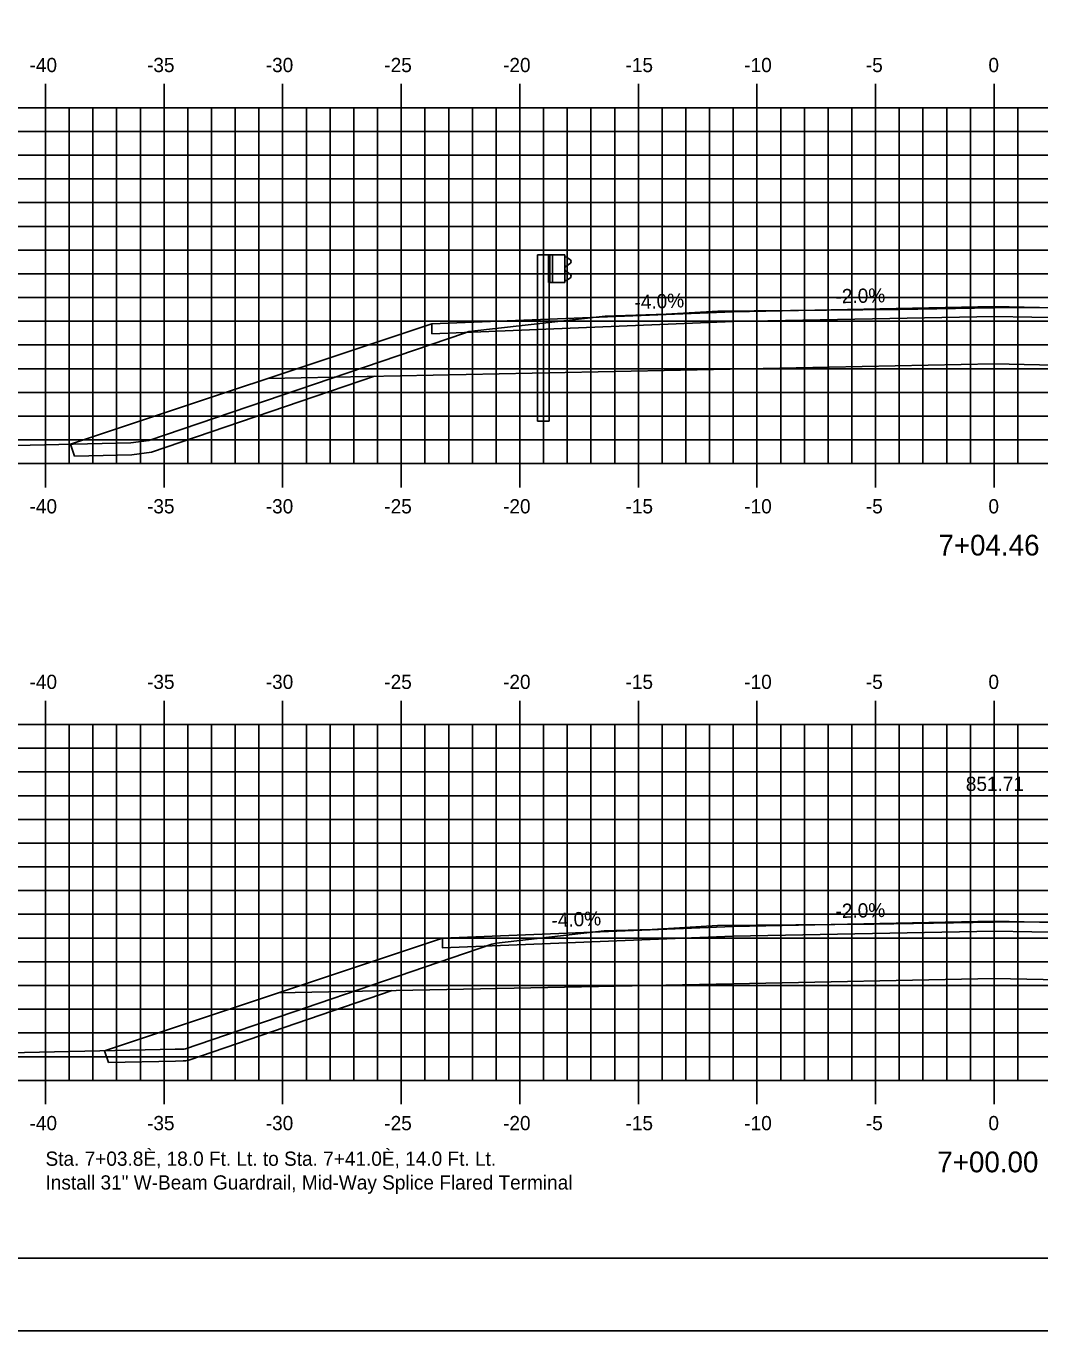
# Model space of a CAD drawing. Extents: x 2194004 to 2194525, y 863888 to 863998.
# Drawn here: x 2194214.2 to 2194256.9, y 863888.4 to 863943.4 of the extents above; entities that cross this region are included whole.
import ezdxf

# ---------------------------------------------------------------- set-up
doc = ezdxf.new("R2010")
doc.units = 0
for name, color, linetype in [('ANNOTATION', 7, 'Continuous'), ('BORDER', 7, 'Continuous'), ('D_Guardrail_Beam_Lt', 7, 'Continuous'), ('H_V ANNOTATION', 7, 'Continuous'), ('MAJOR', 7, 'Continuous'), ('MINOR', 7, 'Continuous'), ('PLOT BOUNDARY', 7, 'Continuous'), ('S_Roadway_Centerline', 7, 'Continuous'), ('TEMPLATE', 7, 'Continuous')]:
    doc.layers.add(name, color=color, linetype=linetype)

msp = doc.modelspace()

# ---------------------------------------------------------------- linework, layer by layer
at = {"layer": 'BORDER'}
msp.add_lwpolyline([(2194179.986, 863891.446), (2194339.986, 863891.446), (2194339.986, 863996.446), (2194179.986, 863996.446)], close=True, dxfattribs=at)
at = {"layer": 'D_Guardrail_Beam_Lt'}
for p, q in [((2194235.725, 863933.739), (2194235.725, 863926.739)), ((2194236.196, 863933.739), (2194235.725, 863933.739)), ((2194236.883, 863933.739), (2194236.196, 863933.739)), ((2194236.196, 863933.739), (2194236.196, 863932.572)), ((2194236.258, 863933.739), (2194236.258, 863932.572)), ((2194236.363, 863933.739), (2194236.363, 863932.572)), ((2194236.883, 863932.572), (2194236.883, 863933.739)), ((2194236.883, 863933.656), (2194236.958, 863933.641)), ((2194236.973, 863933.635), (2194237.117, 863933.535)), ((2194236.888, 863933.191), (2194236.888, 863933.121)), ((2194237.117, 863933.391), (2194236.921, 863933.255)), ((2194236.921, 863933.056), (2194237.117, 863932.92)), ((2194236.196, 863932.572), (2194236.883, 863932.572)), ((2194236.217, 863926.739), (2194236.217, 863932.572)), ((2194236.958, 863932.67), (2194236.883, 863932.656)), ((2194237.117, 863932.777), (2194236.973, 863932.677)), ((2194236.217, 863926.739), (2194235.725, 863926.739))]:
    msp.add_line(p, q, dxfattribs=at)
for centre, major_axis, start_param, end_param in [((2194236.949, 863933.601), (0.0417, 0), 0.959931, 1.376053), ((2194237.066, 863933.463), (0.0877, 0), 5.323254, 7.243116), ((2194236.967, 863933.191), (-0.0789, 0), 5.323254, 6.283185), ((2194236.967, 863933.121), (-0.0789, 0), 6.283185, 7.243116), ((2194237.066, 863932.849), (0.0877, 0), 5.323254, 7.243116), ((2194236.949, 863932.711), (0.0417, 0), 4.907132, 5.323254)]:
    msp.add_ellipse(centre, major_axis=major_axis, ratio=0.995501, start_param=start_param, end_param=end_param, dxfattribs=at)
at = {"layer": 'MAJOR'}
for p, q in [((2194214.986, 863940.948), (2194214.986, 863939.946)), ((2194219.986, 863940.948), (2194219.986, 863939.946)), ((2194224.986, 863940.948), (2194224.986, 863939.946)), ((2194229.986, 863940.948), (2194229.986, 863939.946)), ((2194234.986, 863940.948), (2194234.986, 863939.946)), ((2194239.986, 863940.948), (2194239.986, 863939.946)), ((2194244.986, 863940.948), (2194244.986, 863939.946)), ((2194249.986, 863940.948), (2194249.986, 863939.946)), ((2194254.986, 863940.948), (2194254.986, 863939.946)), ((2194184.986, 863939.946), (2194324.986, 863939.946)), ((2194184.986, 863939.946), (2194324.986, 863939.946)), ((2194214.986, 863924.946), (2194214.986, 863939.946)), ((2194219.986, 863924.946), (2194219.986, 863939.946)), ((2194224.986, 863924.946), (2194224.986, 863939.946)), ((2194229.986, 863924.946), (2194229.986, 863939.946)), ((2194234.986, 863924.946), (2194234.986, 863939.946)), ((2194239.986, 863924.946), (2194239.986, 863939.946)), ((2194244.986, 863924.946), (2194244.986, 863939.946)), ((2194249.986, 863924.946), (2194249.986, 863939.946)), ((2194254.986, 863924.946), (2194254.986, 863939.946)), ((2194184.986, 863934.946), (2194324.986, 863934.946)), ((2194184.986, 863929.946), (2194324.986, 863929.946)), ((2194184.986, 863924.946), (2194324.986, 863924.946)), ((2194214.986, 863923.944), (2194214.986, 863924.946)), ((2194219.986, 863923.944), (2194219.986, 863924.946)), ((2194224.986, 863923.944), (2194224.986, 863924.946)), ((2194229.986, 863923.944), (2194229.986, 863924.946)), ((2194234.986, 863923.944), (2194234.986, 863924.946)), ((2194239.986, 863923.944), (2194239.986, 863924.946)), ((2194244.986, 863923.944), (2194244.986, 863924.946)), ((2194249.986, 863923.944), (2194249.986, 863924.946)), ((2194254.986, 863923.944), (2194254.986, 863924.946)), ((2194214.986, 863914.948), (2194214.986, 863913.946)), ((2194219.986, 863914.948), (2194219.986, 863913.946)), ((2194224.986, 863914.948), (2194224.986, 863913.946)), ((2194229.986, 863914.948), (2194229.986, 863913.946)), ((2194234.986, 863914.948), (2194234.986, 863913.946)), ((2194239.986, 863914.948), (2194239.986, 863913.946)), ((2194244.986, 863914.948), (2194244.986, 863913.946)), ((2194249.986, 863914.948), (2194249.986, 863913.946)), ((2194254.986, 863914.948), (2194254.986, 863913.946)), ((2194184.986, 863913.946), (2194324.986, 863913.946)), ((2194184.986, 863913.946), (2194324.986, 863913.946)), ((2194214.986, 863898.946), (2194214.986, 863913.946)), ((2194219.986, 863898.946), (2194219.986, 863913.946)), ((2194224.986, 863898.946), (2194224.986, 863913.946)), ((2194229.986, 863898.946), (2194229.986, 863913.946)), ((2194234.986, 863898.946), (2194234.986, 863913.946)), ((2194239.986, 863898.946), (2194239.986, 863913.946)), ((2194244.986, 863898.946), (2194244.986, 863913.946)), ((2194249.986, 863898.946), (2194249.986, 863913.946)), ((2194254.986, 863898.946), (2194254.986, 863913.946)), ((2194184.986, 863908.946), (2194324.986, 863908.946)), ((2194184.986, 863903.946), (2194324.986, 863903.946)), ((2194184.986, 863898.946), (2194324.986, 863898.946)), ((2194214.986, 863897.944), (2194214.986, 863898.946)), ((2194219.986, 863897.944), (2194219.986, 863898.946)), ((2194224.986, 863897.944), (2194224.986, 863898.946)), ((2194229.986, 863897.944), (2194229.986, 863898.946)), ((2194234.986, 863897.944), (2194234.986, 863898.946)), ((2194239.986, 863897.944), (2194239.986, 863898.946)), ((2194244.986, 863897.944), (2194244.986, 863898.946)), ((2194249.986, 863897.944), (2194249.986, 863898.946)), ((2194254.986, 863897.944), (2194254.986, 863898.946))]:
    msp.add_line(p, q, dxfattribs=at)
at = {"layer": 'MINOR'}
for p, q in [((2194215.986, 863924.946), (2194215.986, 863939.946)), ((2194216.986, 863924.946), (2194216.986, 863939.946)), ((2194217.986, 863924.946), (2194217.986, 863939.946)), ((2194218.986, 863924.946), (2194218.986, 863939.946)), ((2194220.986, 863924.946), (2194220.986, 863939.946)), ((2194221.986, 863924.946), (2194221.986, 863939.946)), ((2194222.986, 863924.946), (2194222.986, 863939.946)), ((2194223.986, 863924.946), (2194223.986, 863939.946)), ((2194225.986, 863924.946), (2194225.986, 863939.946)), ((2194226.986, 863924.946), (2194226.986, 863939.946)), ((2194227.986, 863924.946), (2194227.986, 863939.946)), ((2194228.986, 863924.946), (2194228.986, 863939.946)), ((2194230.986, 863924.946), (2194230.986, 863939.946)), ((2194231.986, 863924.946), (2194231.986, 863939.946)), ((2194232.986, 863924.946), (2194232.986, 863939.946)), ((2194233.986, 863924.946), (2194233.986, 863939.946)), ((2194235.986, 863924.946), (2194235.986, 863939.946)), ((2194236.986, 863924.946), (2194236.986, 863939.946)), ((2194237.986, 863924.946), (2194237.986, 863939.946)), ((2194238.986, 863924.946), (2194238.986, 863939.946)), ((2194240.986, 863924.946), (2194240.986, 863939.946)), ((2194241.986, 863924.946), (2194241.986, 863939.946)), ((2194242.986, 863924.946), (2194242.986, 863939.946)), ((2194243.986, 863924.946), (2194243.986, 863939.946)), ((2194245.986, 863924.946), (2194245.986, 863939.946)), ((2194246.986, 863924.946), (2194246.986, 863939.946)), ((2194247.986, 863924.946), (2194247.986, 863939.946)), ((2194248.986, 863924.946), (2194248.986, 863939.946)), ((2194250.986, 863924.946), (2194250.986, 863939.946)), ((2194251.986, 863924.946), (2194251.986, 863939.946)), ((2194252.986, 863924.946), (2194252.986, 863939.946)), ((2194253.986, 863924.946), (2194253.986, 863939.946)), ((2194255.986, 863924.946), (2194255.986, 863939.946)), ((2194184.986, 863938.946), (2194324.986, 863938.946)), ((2194184.986, 863937.946), (2194324.986, 863937.946)), ((2194184.986, 863936.946), (2194324.986, 863936.946)), ((2194184.986, 863935.946), (2194324.986, 863935.946)), ((2194184.986, 863933.946), (2194324.986, 863933.946)), ((2194184.986, 863932.946), (2194324.986, 863932.946)), ((2194184.986, 863931.946), (2194324.986, 863931.946)), ((2194184.986, 863930.946), (2194324.986, 863930.946)), ((2194184.986, 863928.946), (2194324.986, 863928.946)), ((2194184.986, 863927.946), (2194324.986, 863927.946)), ((2194184.986, 863926.946), (2194324.986, 863926.946)), ((2194184.986, 863925.946), (2194324.986, 863925.946)), ((2194215.986, 863898.946), (2194215.986, 863913.946)), ((2194216.986, 863898.946), (2194216.986, 863913.946)), ((2194217.986, 863898.946), (2194217.986, 863913.946)), ((2194218.986, 863898.946), (2194218.986, 863913.946)), ((2194220.986, 863898.946), (2194220.986, 863913.946)), ((2194221.986, 863898.946), (2194221.986, 863913.946)), ((2194222.986, 863898.946), (2194222.986, 863913.946)), ((2194223.986, 863898.946), (2194223.986, 863913.946)), ((2194225.986, 863898.946), (2194225.986, 863913.946)), ((2194226.986, 863898.946), (2194226.986, 863913.946)), ((2194227.986, 863898.946), (2194227.986, 863913.946)), ((2194228.986, 863898.946), (2194228.986, 863913.946)), ((2194230.986, 863898.946), (2194230.986, 863913.946)), ((2194231.986, 863898.946), (2194231.986, 863913.946)), ((2194232.986, 863898.946), (2194232.986, 863913.946)), ((2194233.986, 863898.946), (2194233.986, 863913.946)), ((2194235.986, 863898.946), (2194235.986, 863913.946)), ((2194236.986, 863898.946), (2194236.986, 863913.946)), ((2194237.986, 863898.946), (2194237.986, 863913.946)), ((2194238.986, 863898.946), (2194238.986, 863913.946)), ((2194240.986, 863898.946), (2194240.986, 863913.946)), ((2194241.986, 863898.946), (2194241.986, 863913.946)), ((2194242.986, 863898.946), (2194242.986, 863913.946)), ((2194243.986, 863898.946), (2194243.986, 863913.946)), ((2194245.986, 863898.946), (2194245.986, 863913.946)), ((2194246.986, 863898.946), (2194246.986, 863913.946)), ((2194247.986, 863898.946), (2194247.986, 863913.946)), ((2194248.986, 863898.946), (2194248.986, 863913.946)), ((2194250.986, 863898.946), (2194250.986, 863913.946)), ((2194251.986, 863898.946), (2194251.986, 863913.946)), ((2194252.986, 863898.946), (2194252.986, 863913.946)), ((2194253.986, 863898.946), (2194253.986, 863913.946)), ((2194255.986, 863898.946), (2194255.986, 863913.946)), ((2194184.986, 863912.946), (2194324.986, 863912.946)), ((2194184.986, 863911.946), (2194324.986, 863911.946)), ((2194184.986, 863910.946), (2194324.986, 863910.946)), ((2194184.986, 863909.946), (2194324.986, 863909.946)), ((2194184.986, 863907.946), (2194324.986, 863907.946)), ((2194184.986, 863906.946), (2194324.986, 863906.946)), ((2194184.986, 863905.946), (2194324.986, 863905.946)), ((2194184.986, 863904.946), (2194324.986, 863904.946)), ((2194184.986, 863902.946), (2194324.986, 863902.946)), ((2194184.986, 863901.946), (2194324.986, 863901.946)), ((2194184.986, 863900.946), (2194324.986, 863900.946)), ((2194184.986, 863899.946), (2194324.986, 863899.946))]:
    msp.add_line(p, q, dxfattribs=at)
at = {"layer": 'PLOT BOUNDARY'}
msp.add_lwpolyline([(2194171.893, 863888.387), (2194341.893, 863888.387), (2194341.893, 863998.387), (2194171.893, 863998.387)], close=True, dxfattribs=at)
at = {"layer": 'S_Roadway_Centerline'}
for points in [[(2194184.986, 863925.019), (2194197.636, 863925.346), (2194206.425, 863925.541), (2194218.588, 863925.816), (2194219.347, 863925.914), (2194232.657, 863930.448), (2194232.831, 863930.509), (2194232.96, 863930.521), (2194238.587, 863931.16), (2194241.156, 863931.241), (2194243.336, 863931.371), (2194250.982, 863931.437), (2194254.953, 863931.509), (2194262.373, 863931.527), (2194266.278, 863931.497), (2194268.391, 863931.477), (2194272.752, 863931.249), (2194275.855, 863931.097), (2194280.904, 863928.615), (2194281.523, 863928.402), (2194284.108, 863928.415)], [(2194184.986, 863899.44), (2194193.736, 863899.667), (2194220.459, 863900.26), (2194220.779, 863900.267), (2194220.835, 863900.267), (2194220.887, 863900.279), (2194220.888, 863900.279), (2194233.802, 863904.693), (2194234.003, 863904.728), (2194238.543, 863905.244), (2194240.565, 863905.308), (2194243.32, 863905.472), (2194249.921, 863905.529), (2194254.949, 863905.619), (2194261.358, 863905.635), (2194266.294, 863905.597), (2194268.965, 863905.572), (2194272.648, 863905.379), (2194276.655, 863905.184), (2194281.436, 863902.833), (2194282.094, 863902.5), (2194284.53, 863902.509)]]:
    msp.add_lwpolyline(points, dxfattribs=at)
at = {"layer": 'TEMPLATE'}
for p, q in [((2194243.986, 863931.346), (2194231.279, 863930.837)), ((2194237.986, 863931.106), (2194243.986, 863931.346)), ((2194243.986, 863931.346), (2194254.986, 863931.566)), ((2194254.986, 863931.566), (2194243.986, 863931.346)), ((2194265.986, 863931.346), (2194254.986, 863931.566)), ((2194231.279, 863930.837), (2194216.043, 863925.759)), ((2194237.986, 863931.106), (2194237.986, 863931.106)), ((2194254.986, 863931.149), (2194243.986, 863930.929)), ((2194265.986, 863930.929), (2194254.986, 863931.149)), ((2194254.986, 863929.149), (2194224.378, 863928.537)), ((2194280.701, 863928.635), (2194254.986, 863929.149)), ((2194216.043, 863925.759), (2194216.209, 863925.262)), ((2194243.986, 863905.436), (2194254.986, 863905.656)), ((2194254.986, 863905.656), (2194243.986, 863905.436)), ((2194265.986, 863905.436), (2194254.986, 863905.656)), ((2194231.727, 863904.945), (2194217.472, 863900.194)), ((2194243.986, 863905.019), (2194254.986, 863905.239)), ((2194265.986, 863905.019), (2194254.986, 863905.239))]:
    msp.add_line(p, q, dxfattribs=at)
for points in [[(2194243.986, 863930.929), (2194231.279, 863930.421), (2194231.279, 863930.837)], [(2194216.209, 863925.262), (2194218.626, 863925.317), (2194219.461, 863925.425), (2194228.859, 863928.627)], [(2194231.727, 863904.945), (2194243.986, 863905.436)], [(2194231.727, 863904.945), (2194231.727, 863904.529), (2194243.986, 863905.019)], [(2194224.797, 863902.635), (2194243.986, 863903.019), (2194254.986, 863903.239), (2194265.986, 863903.019), (2194281.297, 863902.713)], [(2194217.638, 863899.697), (2194220.47, 863899.76), (2194220.785, 863899.767), (2194220.893, 863899.767), (2194221.008, 863899.793), (2194221.034, 863899.8), (2194229.61, 863902.732)], [(2194217.638, 863899.697), (2194217.472, 863900.194)]]:
    msp.add_lwpolyline(points, dxfattribs=at)

# ---------------------------------------------------------------- texts
at = {"layer": 'ANNOTATION'}
for s, rotation, p in [('-2.0%', 1.1458, (2194248.304, 863931.699)), ('-4.0%', 2.2906, (2194239.831, 863931.447)), ('-4.0%', 2.2906, (2194236.331, 863905.397)), ('-2.0%', 1.1458, (2194248.304, 863905.789))]:
    msp.add_text(s, height=0.6, rotation=rotation, dxfattribs=at).set_placement(p)
for s, p in [('851.71', (2194253.793, 863911.146)), ('Sta. 7+03.8È, 18.0 Ft. Lt. to Sta. 7+41.0È, 14.0 Ft. Lt.', (2194214.986, 863895.346)), ('Install 31" W-Beam Guardrail, Mid-Way Splice Flared Terminal', (2194214.986, 863894.344))]:
    msp.add_text(s, height=0.6, dxfattribs=at).set_placement(p)
at = {"layer": 'H_V ANNOTATION'}
for s, height, p in [('-40', 0.6, (2194214.312, 863941.446)), ('-35', 0.6, (2194219.266, 863941.446)), ('-30', 0.6, (2194224.274, 863941.446)), ('-25', 0.6, (2194229.272, 863941.446)), ('-20', 0.6, (2194234.28, 863941.446)), ('-15', 0.6, (2194239.443, 863941.446)), ('-10', 0.6, (2194244.451, 863941.446)), ('-5', 0.6, (2194249.577, 863941.446)), ('0', 0.6, (2194254.745, 863941.446)), ('-40', 0.6, (2194214.312, 863922.846)), ('-35', 0.6, (2194219.266, 863922.846)), ('-30', 0.6, (2194224.274, 863922.846)), ('-25', 0.6, (2194229.272, 863922.846)), ('-20', 0.6, (2194234.28, 863922.846)), ('-15', 0.6, (2194239.443, 863922.846)), ('-10', 0.6, (2194244.451, 863922.846)), ('-5', 0.6, (2194249.577, 863922.846)), ('0', 0.6, (2194254.745, 863922.846)), ('7+04.46', 0.875, (2194252.638, 863921.071)), ('-40', 0.6, (2194214.312, 863915.446)), ('-35', 0.6, (2194219.266, 863915.446)), ('-30', 0.6, (2194224.274, 863915.446)), ('-25', 0.6, (2194229.272, 863915.446)), ('-20', 0.6, (2194234.28, 863915.446)), ('-15', 0.6, (2194239.443, 863915.446)), ('-10', 0.6, (2194244.451, 863915.446)), ('-5', 0.6, (2194249.577, 863915.446)), ('0', 0.6, (2194254.745, 863915.446)), ('-40', 0.6, (2194214.312, 863896.846)), ('-35', 0.6, (2194219.266, 863896.846)), ('-30', 0.6, (2194224.274, 863896.846)), ('-25', 0.6, (2194229.272, 863896.846)), ('-20', 0.6, (2194234.28, 863896.846)), ('-15', 0.6, (2194239.443, 863896.846)), ('-10', 0.6, (2194244.451, 863896.846)), ('-5', 0.6, (2194249.577, 863896.846)), ('0', 0.6, (2194254.745, 863896.846)), ('7+00.00', 0.875, (2194252.591, 863895.071))]:
    msp.add_text(s, height=height, dxfattribs=at).set_placement(p)
at = {"layer": 'TEMPLATE'}
for s, p in [('C', (2194254.948, 863931.509)), ('L', (2194254.953, 863931.501))]:
    msp.add_text(s, height=0.0146, dxfattribs=at).set_placement(p)

doc.saveas('drawing.dxf')
